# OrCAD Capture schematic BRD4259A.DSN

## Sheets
1 02: RF, Antenna & Power: size A3; title: EFR32FG14 2.4 GHz / 434 MHz 10 dBm Radio Board; rev: A01; note: BRD4259A; note: JSH; note: JNO
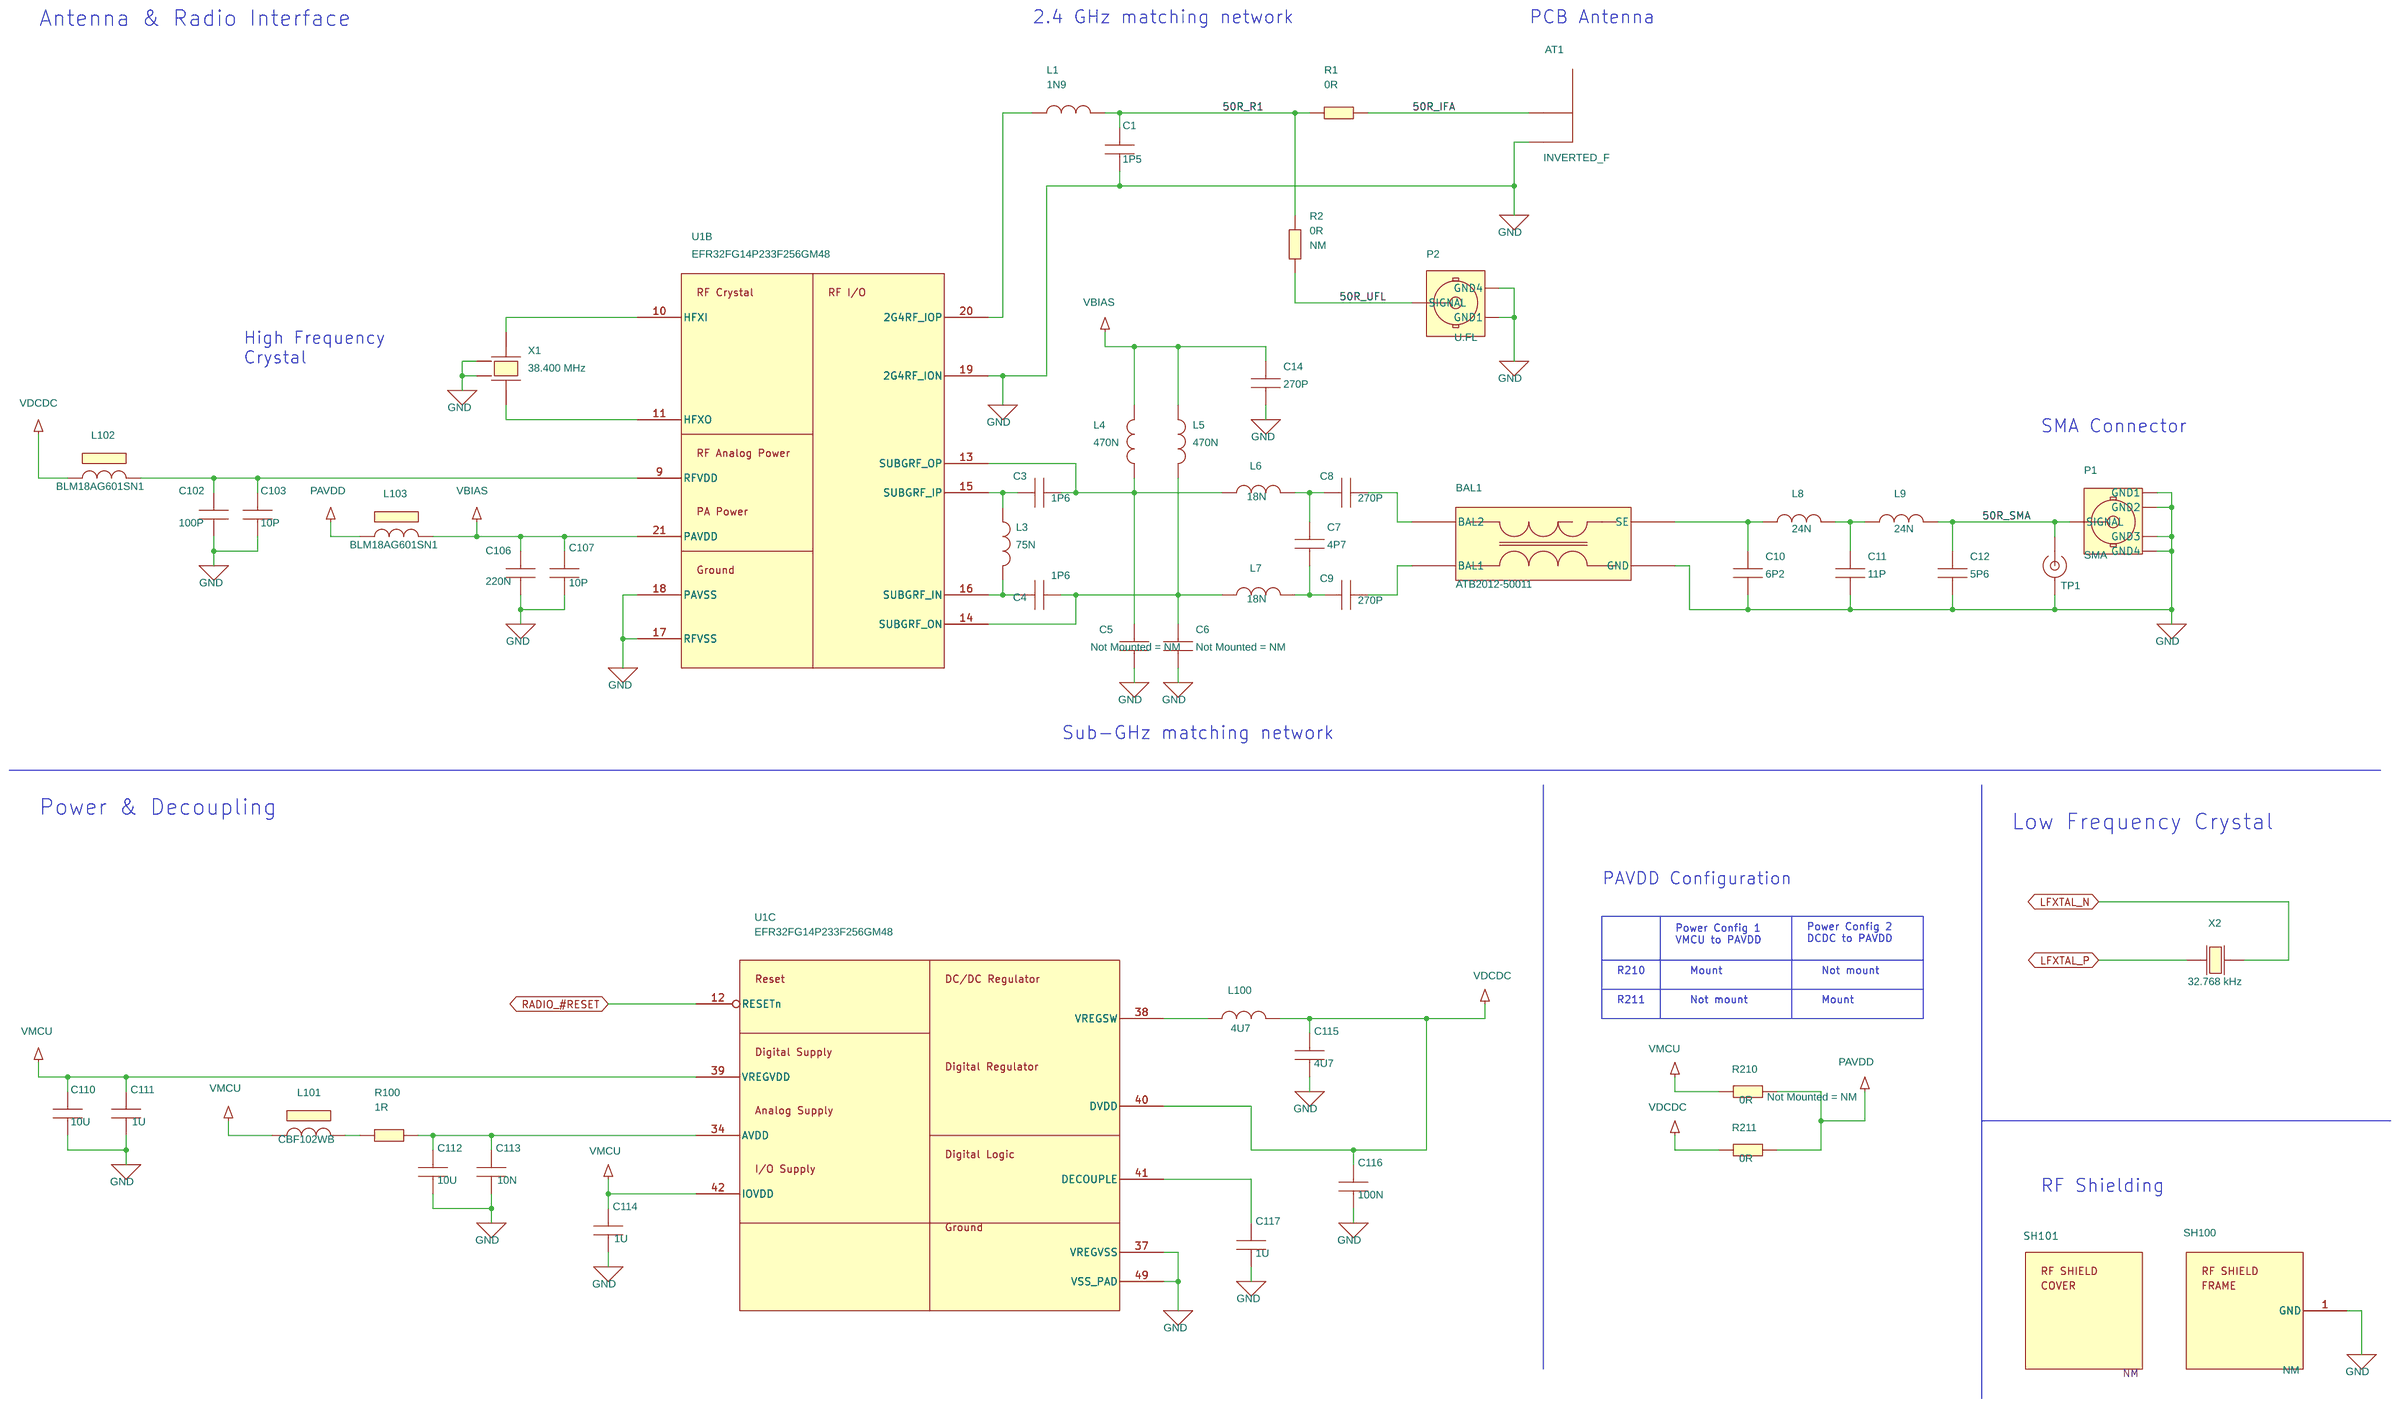
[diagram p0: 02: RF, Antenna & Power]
2 01: Title Page: company: Silicon Labs
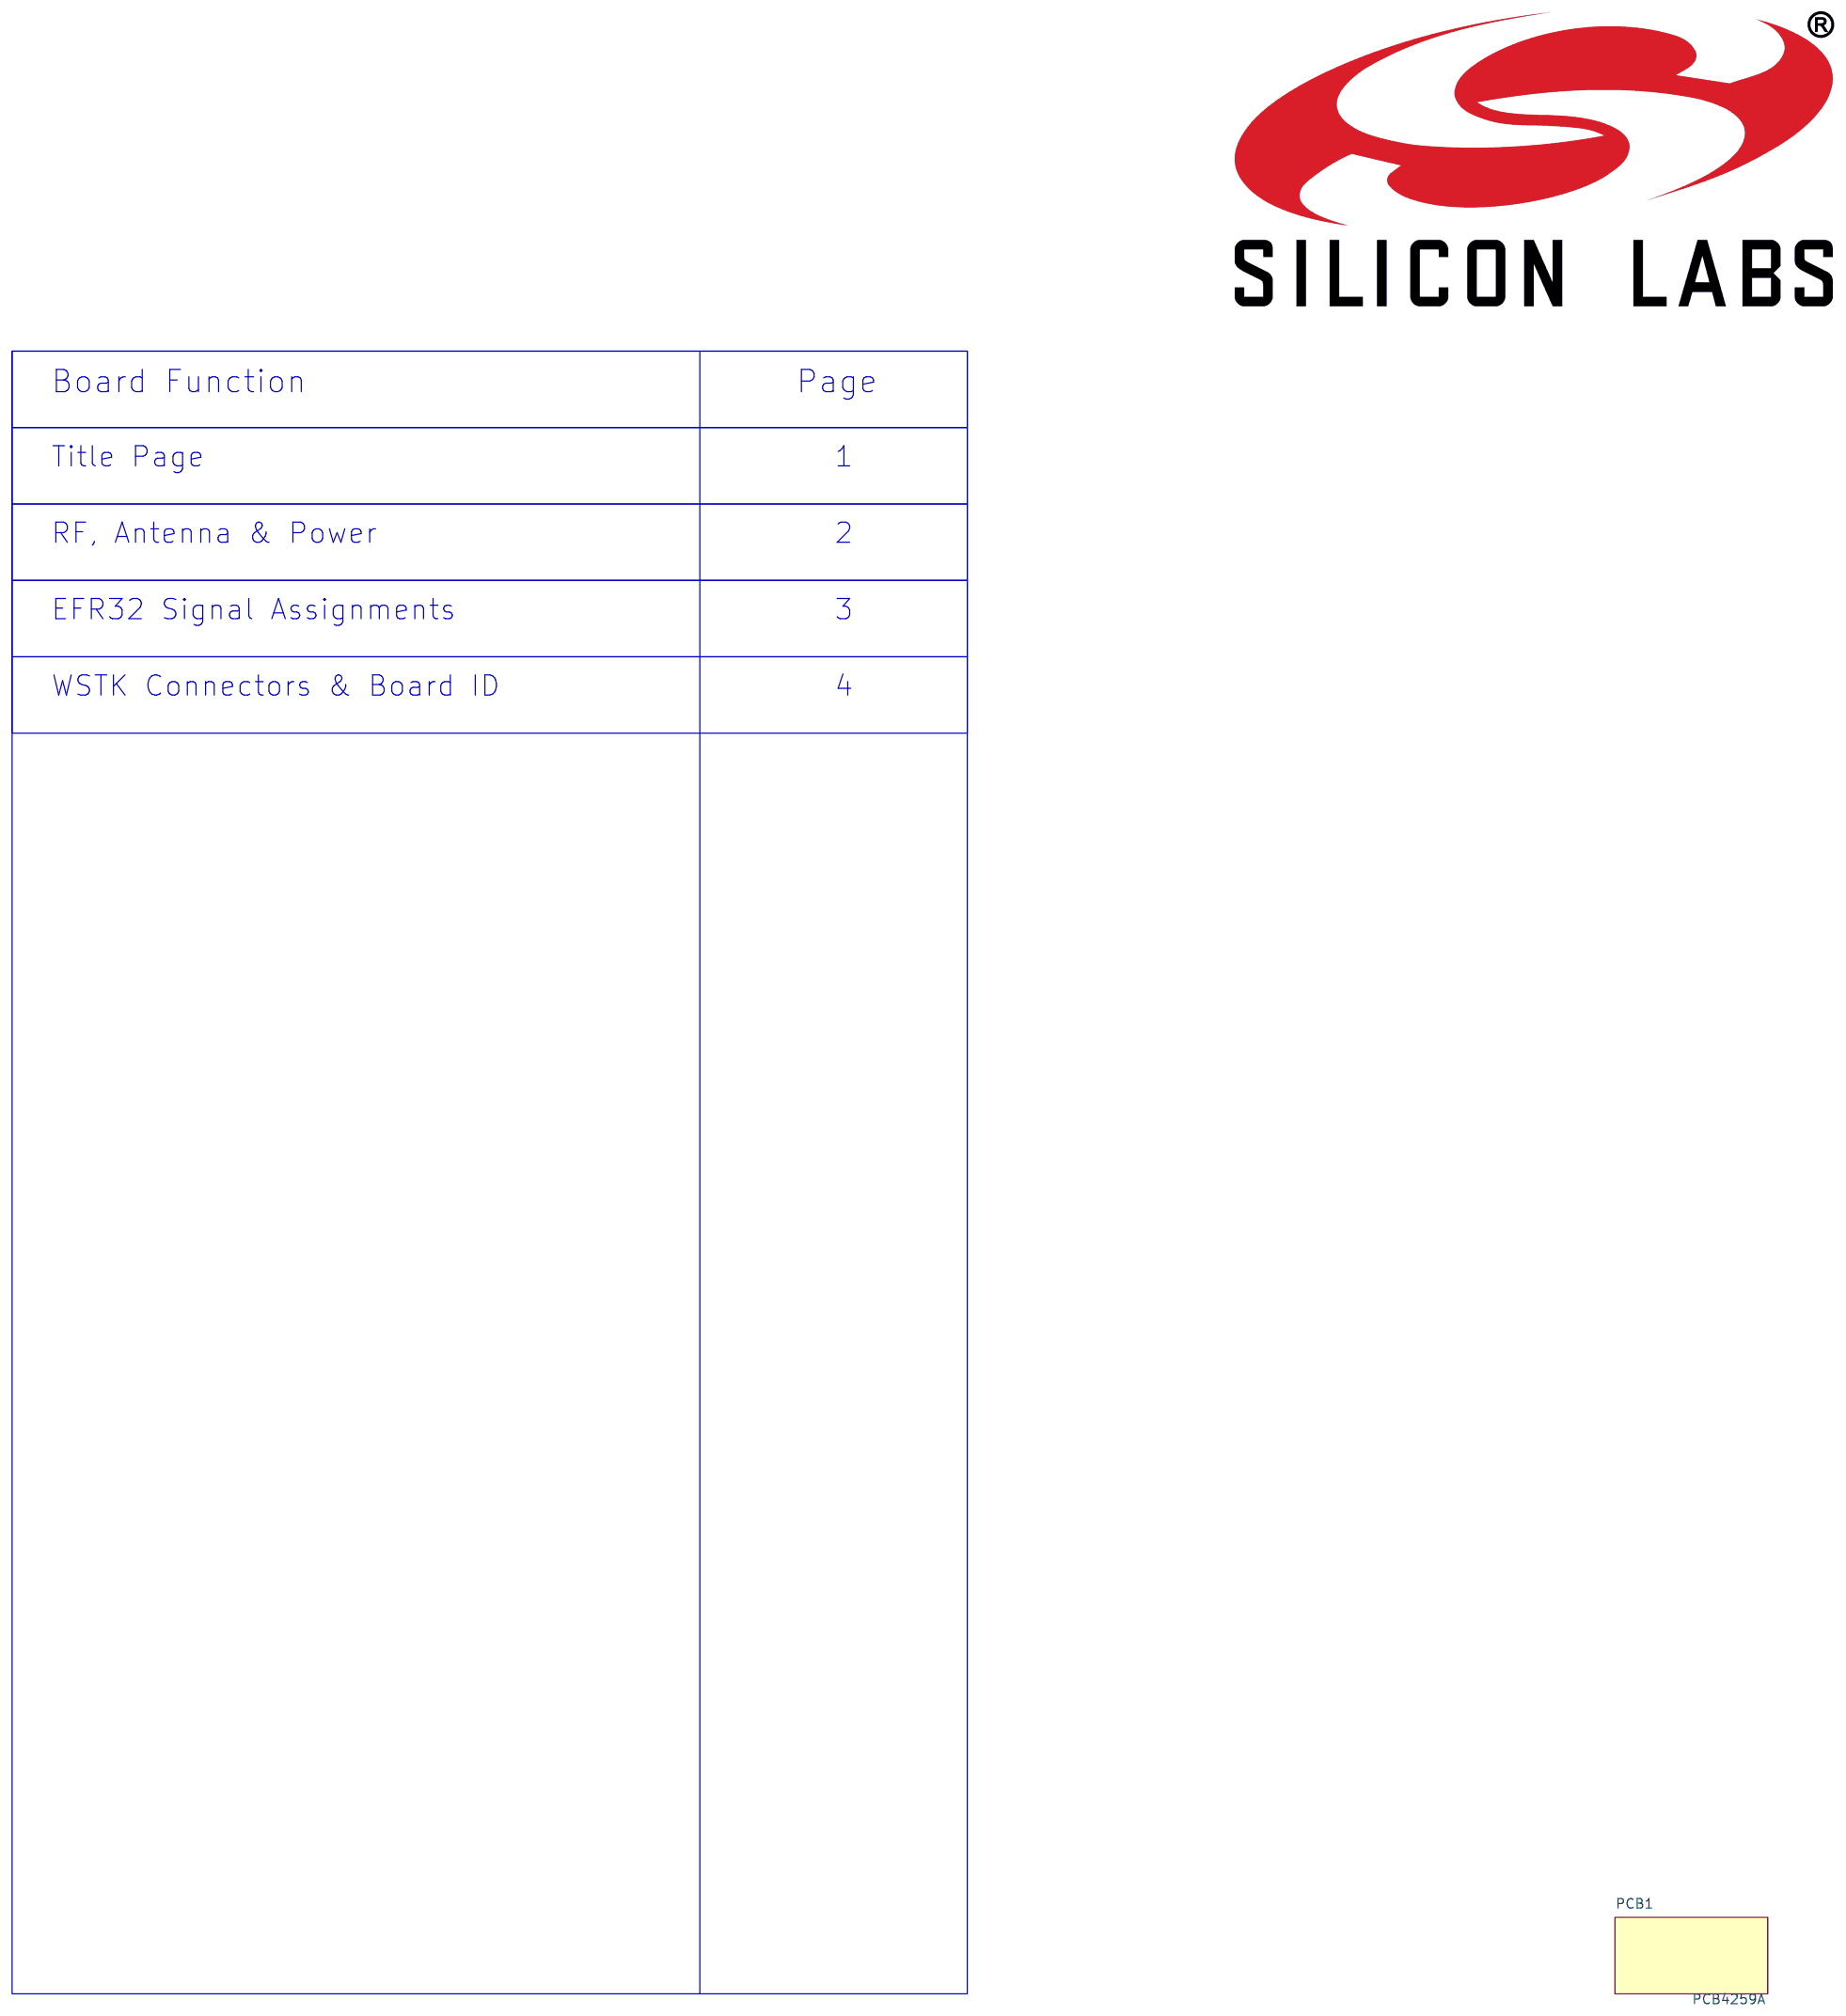
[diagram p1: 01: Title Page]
3 03: EFR32 Signal Assignments: size A3
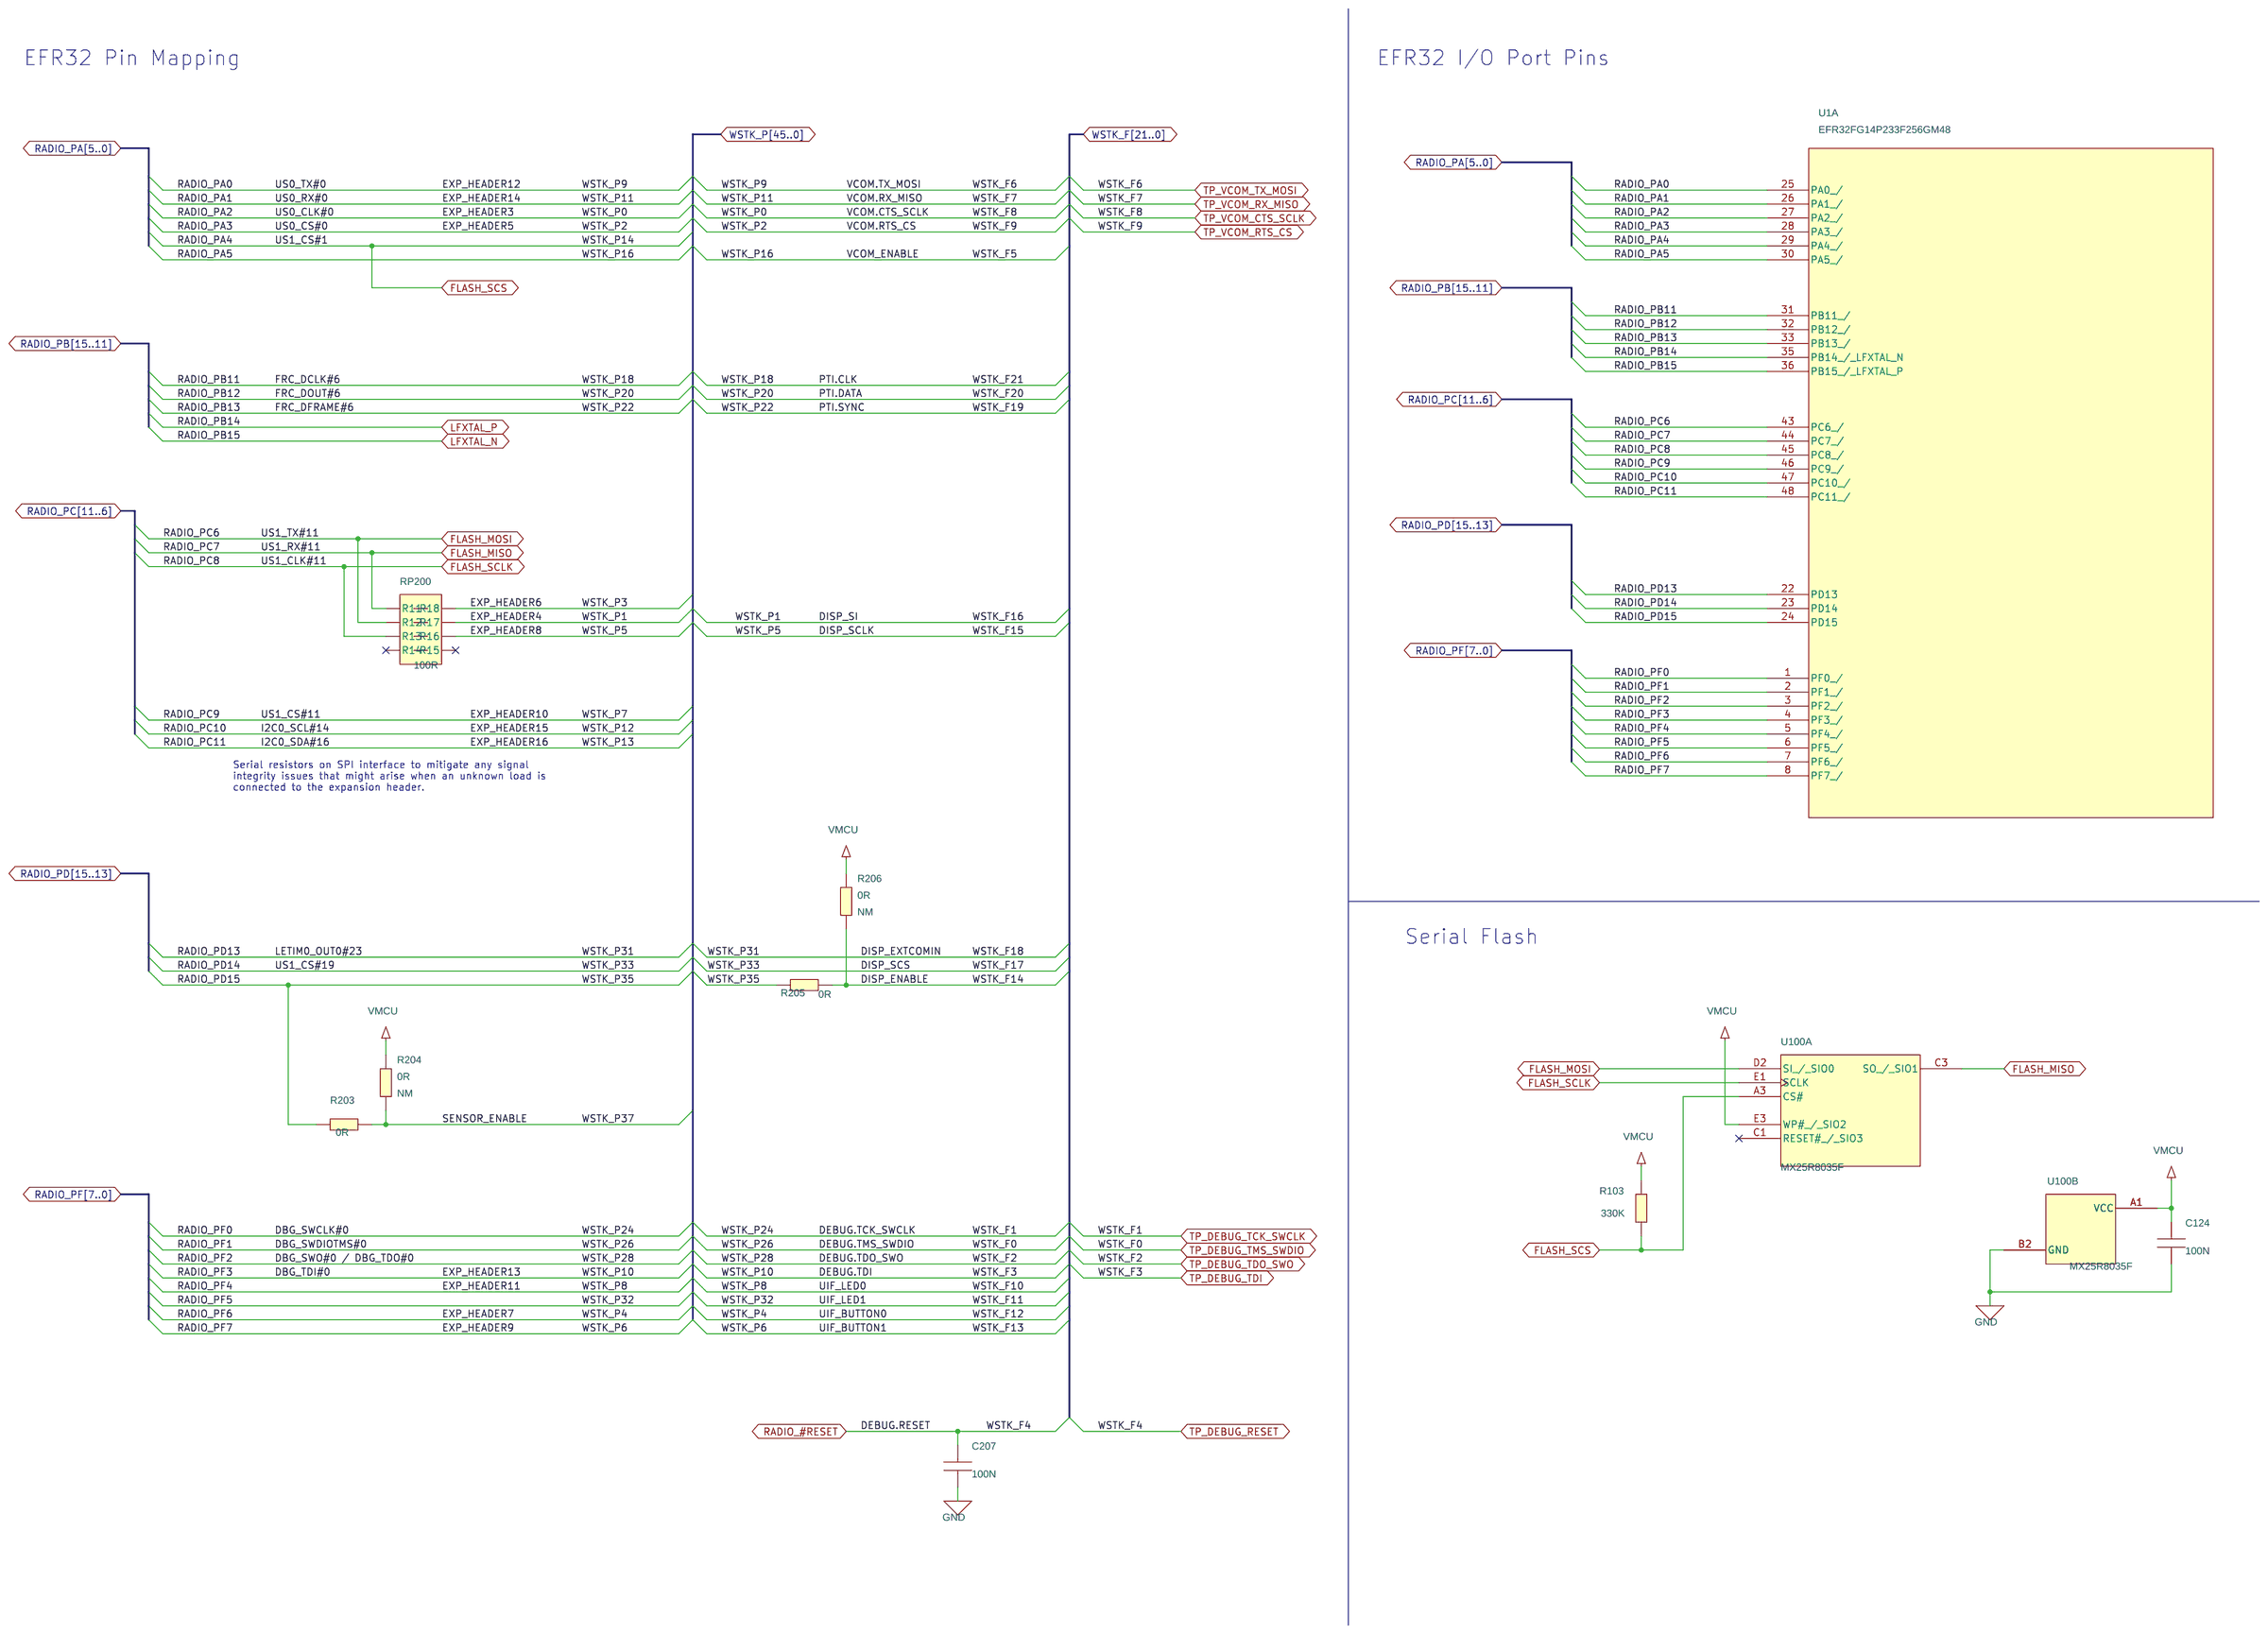
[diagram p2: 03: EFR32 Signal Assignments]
4 04: WSTK Connectors & Board ID: size A3
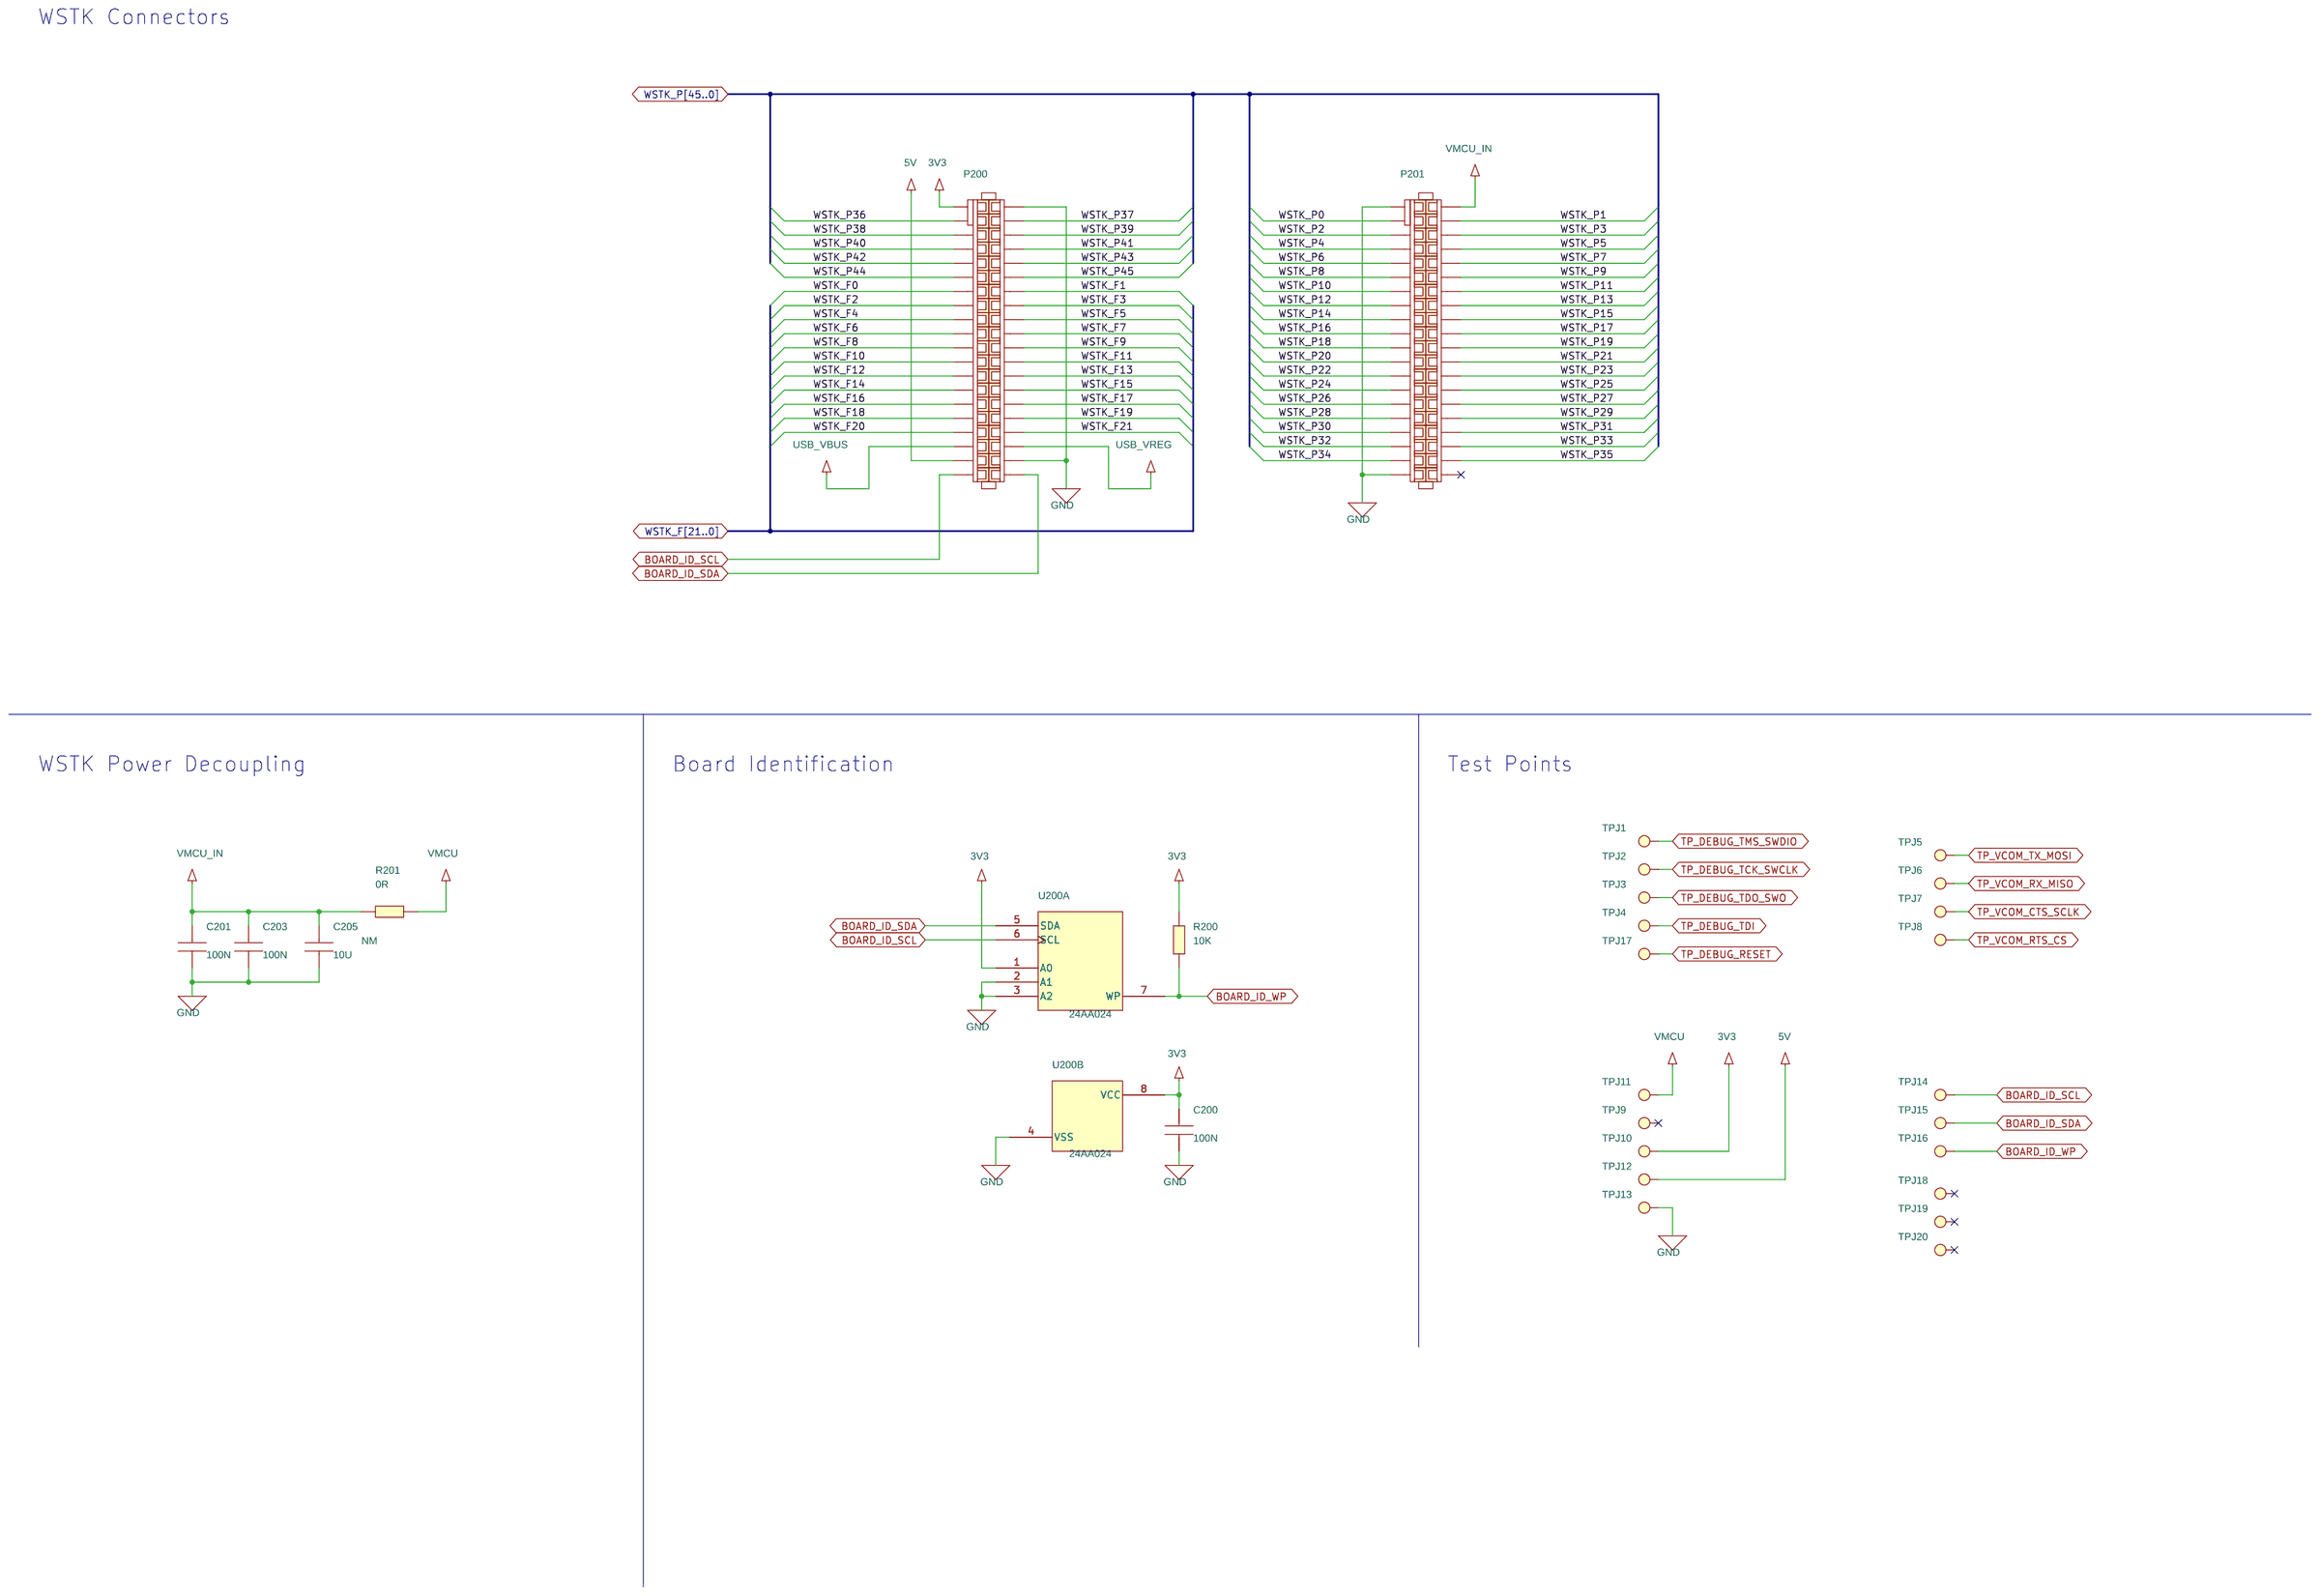
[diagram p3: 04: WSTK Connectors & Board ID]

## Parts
sheet 01: Title Page
PCB1  PCB4259A  [N/A]
sheet 02: RF, Antenna & Power
AT1  INVERTED_F  [EM358x_INVERTED_F]
BAL1  ATB2012-50011  [TDK_ATB2012]
C1  1P5  [C0402_L]
C3  1P6  [C0402_L]
C4  1P6  [C0402_L]
C5  Unused  [C0402_L]
C6  Unused  [C0402_L]
C7  4P7  [C0402_L]
C8  270P  [C0402_L]
C9  270P  [C0402_L]
C10  6P2  [C0402_L]
C11  11P  [C0402_L]
C12  5P6  [C0402_L]
C14  270P  [C0402_L]
C102  100P  [C0402_L]
C103  10P  [C0402_L]
C106  220N  [C0402_L]
C107  10P  [C0402_L]
C110  10U  [C0603_L]
C111  1U  [C0402_L]
C112  10U  [C0603_L]
C113  10N  [C0402_L]
C114  1U  [C0402_L]
C115  4U7  [C0402_L]
C116  100N  [C0402_L]
C117  1U  [C0402_L]
L1  1N9  [COIL_0402_L]
L3  75N  [COIL_0603_L]
L4  470N  [COIL_0603_L]
L5  470N  [COIL_0603_L]
L6  18N  [COIL_0402_L]
L7  18N  [COIL_0402_L]
L8  24N  [COIL_0402_L]
L9  24N  [COIL_0402_L]
L100  4U7  [COIL_MUR_LQH3NP_1212]
L101  CBF102WB  [WURTH_CBF_0603]
L102  BLM18AG601SN1  [COIL_MUR_BLM18_0603]
L103  BLM18AG601SN1  [COIL_MUR_BLM18_0603]
P1  SMA  [TE_SMA_TH_1814832]
P2  U.FL  [HIROSE_U.FL-R-SMT-1]
R1  0R  [R0402_L]
R2  0R  [R0402_L]
R100  1R  [R0402_L]
R210  0R  [R0402_L]
R211  0R  [R0402_L]
SH100  RF_SHIELD_FRAME_BMI-S-203-F  [LAIRD_BMI-S-203-F]
SH101  RF_SHIELD_COVER_BMI-S-203-C
TP1  RF_TEST_POINT  [TP_INGUN_50OHM_PARTIAL]
X1  38.400 MHz  [X_SSS_DSX211SH_2.05X1.65-4]
X2  32.768 kHz  [X_MCS_CM8V-T1A]
sheet 03: EFR32 Signal Assignments
C124  100N  [C0402_L]
C207  100N  [C0402_L]
R103  330K  [R0402_L]
R203  0R  [R0402_L]
R204  0R  [R0402_L]
R205  0R  [R0402_L]
R206  0R  [R0402_L]
RP200  100R  [RES_MNR04-8]
U1  EFR32FG14P233F256GM48  [QFN48_M050_SQ7.0_EP_SL_L]  (sections A,B,C)
U100  MX25R8035F  [BGA8_M040_1.24x1.75_WLCSP]  (sections A,B)
sheet 04: WSTK Connectors & Board ID
C200  100N  [C0402_L]
C201  100N  [C0402_L]
C203  100N  [C0402_L]
C205  10U  [C0805_L]
P200  SOCKET_2X20_1.27MM_SMD  [SAM_SFC-120-T2-D-A-2X20_SNUM]
P201  SOCKET_2X20_1.27MM_SMD  [SAM_SFC-120-T2-D-A-2X20_SNUM]
R200  10K  [T_0402]
R201  0R  [R0402_L]
TPJ1  TPJ_SMD  [TP_1.0_SMD]
TPJ2  TPJ_SMD  [TP_1.0_SMD]
TPJ3  TPJ_SMD  [TP_1.0_SMD]
TPJ4  TPJ_SMD  [TP_1.0_SMD]
TPJ5  TPJ_SMD  [TP_1.0_SMD]
TPJ6  TPJ_SMD  [TP_1.0_SMD]
TPJ7  TPJ_SMD  [TP_1.0_SMD]
TPJ8  TPJ_SMD  [TP_1.0_SMD]
TPJ9  TPJ_SMD  [TP_1.0_SMD]
TPJ10  TPJ_SMD  [TP_1.0_SMD]
TPJ11  TPJ_SMD  [TP_1.0_SMD]
TPJ12  TPJ_SMD  [TP_1.0_SMD]
TPJ13  TPJ_SMD  [TP_1.0_SMD]
TPJ14  TPJ_SMD  [TP_1.0_SMD]
TPJ15  TPJ_SMD  [TP_1.0_SMD]
TPJ16  TPJ_SMD  [TP_1.0_SMD]
TPJ17  TPJ_SMD  [TP_1.0_SMD]
TPJ18  TPJ_SMD  [TP_1.0_SMD]
TPJ19  TPJ_SMD  [TP_1.0_SMD]
TPJ20  TPJ_SMD  [TP_1.0_SMD]
U200  24AA024  [TDFN8_M050_2.0X3.0_EP]  (sections A,B)

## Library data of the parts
PCB1 = PCB: Mfg #: PCB4259A Rev. A00
AT1 = ANT_INVERTED_F
BAL1 = ATB2012-50011
C1 = C0402: Mfg: Murata; Mfg #: GRM1555C1H1R5WA01D; Technology: C0G; Tolerance: ±0.05P
C3 C4 = C0402: Mfg: Murata; Mfg #: GRM1555C1H1R6WA01D; Technology: C0G; Tolerance: ±0.05P
C5 C6 = C0402: Not Mounted: NM
C7 = C0402: Mfg: Murata; Mfg #: GRM1555C1H4R7WA01D; Technology: C0G; Tolerance: ±0.05P
C8 C9 C14 = C0402: Mfg: Murata; Mfg #: GRM1555C1H271FA01D; Technology: C0G; Tolerance: ±1%
C10 = C0402: Mfg: Murata; Mfg #: GRM1555C1H6R2BA01D; Technology: C0G; Tolerance: ±0.1P
C11 = C0402: Mfg: Murata; Mfg #: GRM1555C1H110GA01D; Technology: C0G; Tolerance: ±2%
C12 = C0402: Mfg: Murata; Mfg #: GRM1555C1H5R6WA01D; Technology: C0G; Tolerance: ±0.05pF
C102 C103 C107 = C0402: Rating: 50V; Technology: C0G; Tolerance: 5%
C106 C113 C116 C124 C200 C201 C203 C207 = C0402: Rating: 16V; Technology: X7R; Tolerance: 10%
C110 C112 = C0603: Rating: 6.3V; Technology: X5R; Tolerance: 20%
C111 C114 C117 = C0402: Rating: 25V; Technology: X5R; Tolerance: 10%
C115 = C0402: Rating: 6.3V; Technology: X5R; Tolerance: 10%
L1 = L0402: Mfg: Murata; Mfg #: LQP15MN1N9W02D; Tolerance: ±0.05N
L3 = L0603: Mfg: Murata; Mfg #: LQW18AN75NG00D; Tolerance: ±2%
L4 L5 = L0603: Mfg: Murata; Mfg #: LQW18CNR47J00D; Tolerance: ±5%
L6 L7 = L0402: Mfg: Murata; Mfg #: LQW15AN18NG00D; Tolerance: ±2%
L8 L9 = L0402: Mfg: Murata; Mfg #: LQW15AN24NG00D; Tolerance: ±2%
L100 = LQH3NP: Mfg #: LQH3NPN4R7MM0L
L101 = CBF102WB
L102 L103 = BLM18AG
P1 = SMA_TH
P2 = HIROSE_U.FL
R1 R100 R103 R200 R201 R203 R205 R211 = R0402
R2 R204 R206 R210 = R0402: Not Mounted: NM
SH100 = RF_SHIELD_FRAME_BMI-S-203-F: Not Mounted: NM
SH101 = RF_SHIELD_COVER_BMI-S-203-C: Not Mounted: NM
TP1 = TP_RF
X1 = DSX211SH: Mfg: KDS; Mfg #: DSX211SH 1ZZNAE38400AB0A
X2 = CM8V-T1A: Mfg: KDS; Mfg #: DST210 1TJG125DP1A0012
RP200 = MNR04M0APJ101
U1 = EFR32-DUALBAND-QFN48: Mfg #: EFR32FG14P233F256GM48-BR
U100 = MX25R8035
C205 = C0805: Not Mounted: NM; Rating: 10V; Technology: X5R; Tolerance: 10%
P200 P201 = SOCKET_2X20_1.27MM_SMD
TPJ1-TPJ20 = TPJ_SMD
U200 = 24AA024

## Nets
3V3: C200.1 P200.1 R200.2 TPJ10.1(TP) U200.1(A0) U200.8(VCC)
5V: P200.37 TPJ12.1(TP)
GND: AT1.2(GND) BAL1.2(GND) C1.1 C5.2 C6.2 C10.2 C11.2 C12.2 C14.2 C102.2 C103.2 C106.2 C107.2 C110.2 C111.2 C112.2 C113.2 C114.2 C115.2 C116.2 C117.2 C124.2 C200.2 C201.2 C203.2 C205.2 C207.2 P1.2(GND1) P1.3(GND2) P1.4(GND3) P1.5(GND4) P2.2(GND1) P2.3(GND4) P200.2 P200.38 P201.1 P201.39 SH100.1(GND) TP1.2(GND) TPJ13.1(TP) U1.17(RFVSS) U1.18(PAVSS) U1.19(2G4RF_ION) U1.37(VREGVSS) U1.49(VSS_PAD) U100.B2(GND) U200.2(A1) U200.3(A2) U200.4(VSS) X1.2 X1.4
50R_IFA: AT1.1(ANT) R1.2
50R_R1: C1.2 L1.2 R1.1 R2.1
50R_SMA: C12.1 L9.1 P1.1(SIGNAL) TP1.1(RF)
50R_UFL: P2.1(SIGNAL) R2.2
BOARD_ID_SCL: P200.39 TPJ14.1(TP) U200.6(SCL)
BOARD_ID_SDA: P200.40 TPJ15.1(TP) U200.5(SDA)
BOARD_ID_WP: R200.1 TPJ16.1(TP) U200.7(WP)
FLASH_MISO: RP200.1(R11) U1.44(PC7_/) U100.C3(SO_/_SIO1)
FLASH_MOSI: RP200.2(R12) U1.43(PC6_/) U100.D2(SI_/_SIO0)
FLASH_SCLK: RP200.3(R13) U1.45(PC8_/) U100.E1(SCLK)
FLASH_SCS: P201.17 R103.2 U1.29(PA4_/) U100.A3(CS#)
LFXTAL_N: U1.36(PB15_/_LFXTAL_P) X2.1
LFXTAL_P: U1.35(PB14_/_LFXTAL_N) X2.2
PAVDD: L103.1 R210.1 R211.1
RADIO_#RESET: C207.1 P200.17 TPJ17.1(TP) U1.12(RESETn)
RADIO_PA0: P200.19 P201.12 TPJ5.1(TP) U1.25(PA0_/)
RADIO_PA1: P200.20 P201.14 TPJ6.1(TP) U1.26(PA1_/)
RADIO_PA2: P200.21 P201.3 TPJ7.1(TP) U1.27(PA2_/)
RADIO_PA3: P200.22 P201.5 TPJ8.1(TP) U1.28(PA3_/)
RADIO_PA5: P200.18 P201.19 U1.30(PA5_/)
RADIO_PB11: P200.34 P201.21 U1.31(PB11_/)
RADIO_PB12: P200.33 P201.23 U1.32(PB12_/)
RADIO_PB13: P200.32 P201.25 U1.33(PB13_/)
RADIO_PC9: P201.10 U1.46(PC9_/)
RADIO_PC10: P201.15 U1.47(PC10_/)
RADIO_PC11: P201.16 U1.48(PC11_/)
RADIO_PD13: P200.31 P201.34 U1.22(PD13)
RADIO_PD14: P200.30 P201.36 U1.23(PD14)
RADIO_PD15: P201.38 R203.1 R205.1 U1.24(PD15)
RADIO_PF0: P200.14 P201.27 TPJ2.1(TP) U1.1(PF0_/)
RADIO_PF1: P200.13 P201.29 TPJ1.1(TP) U1.2(PF1_/)
RADIO_PF2: P200.15 P201.31 TPJ3.1(TP) U1.3(PF2_/)
RADIO_PF3: P200.16 P201.13 TPJ4.1(TP) U1.4(PF3_/)
RADIO_PF4: P200.23 P201.11 U1.5(PF4_/)
RADIO_PF5: P200.24 P201.35 U1.6(PF5_/)
RADIO_PF6: P200.25 P201.7 U1.7(PF6_/)
RADIO_PF7: P200.26 P201.9 U1.8(PF7_/)
USB_VBUS: P200.35
USB_VREG: P200.36
VBIAS: C14.1 C106.1 C107.1 L4.1 L5.1 L103.2 U1.21(PAVDD)
VDCDC: C115.1 C116.1 L100.2 L102.1 R211.2 U1.40(DVDD)
VMCU: C110.1 C111.1 C114.1 C124.1 L101.1 R103.1 R201.2 R204.1 R206.1 R210.2 TPJ11.1(TP) U1.39(VREGVDD) U1.42(IOVDD) U100.A1(VCC) U100.E3(WP#_/_SIO2)
VMCU_IN: C201.1 C203.1 C205.1 P201.2 R201.1
WSTK_F14: P200.27 R205.2 R206.2
WSTK_F15: P200.28 P201.8 RP200.6(R16)
WSTK_F16: P200.29 P201.4 RP200.7(R17)
WSTK_P3: P201.6 RP200.8(R18)
WSTK_P15: P201.18
WSTK_P17: P201.20
WSTK_P19: P201.22
WSTK_P21: P201.24
WSTK_P23: P201.26
WSTK_P25: P201.28
WSTK_P27: P201.30
WSTK_P29: P201.32
WSTK_P30: P201.33
WSTK_P34: P201.37
WSTK_P36: P200.3
WSTK_P37: P200.4 R203.2 R204.2
WSTK_P38: P200.5
WSTK_P39: P200.6
WSTK_P40: P200.7
WSTK_P41: P200.8
WSTK_P42: P200.9
WSTK_P43: P200.10
WSTK_P44: P200.11
WSTK_P45: P200.12
N17603239: L1.1 U1.20(2G4RF_IOP)
N17603622: U1.11(HFXO) X1.1
N17603629: U1.10(HFXI) X1.3
N17769146: C117.1 U1.41(DECOUPLE)
N17769405: L100.1 U1.38(VREGSW)
N17853356: C102.1 C103.1 L102.2 U1.9(RFVDD)
N17857389: L101.2 R100.1
N17857391: C112.1 C113.1 R100.2 U1.34(AVDD)
N18038575: C3.2 L3.1 U1.15(SUBGRF_IP)
N18038577: C4.2 L3.2 U1.16(SUBGRF_IN)
N18038619: C3.1 C5.1 L4.2 L6.2 U1.13(SUBGRF_OP)
N18038621: C4.1 C6.1 L5.2 L7.2 U1.14(SUBGRF_ON)
N18038649: C7.1 C8.2 L6.1
N18038653: C7.2 C9.2 L7.1
N18038740: C11.1 L8.1 L9.2
N18038746: BAL1.1(SE) C10.1 L8.2
N18038850: BAL1.4(BAL2) C8.1
N18038856: BAL1.3(BAL1) C9.1

Not connected (* = marked no-connect by the designer): P201 40*; RP200 4(R14)* 5(R15)*; TPJ9 1(TP)*; TPJ18 1(TP)*; TPJ19 1(TP)*; TPJ20 1(TP)*; U100 C1(RESET#_/_SIO3)*

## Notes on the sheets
sheet 1
- Antenna & Radio Interface
- 2.4 GHz matching network
- PCB Antenna
- High Frequency
  Crystal
- SMA Connector
- Sub-GHz matching network
- Power & Decoupling
- Low Frequency Crystal
- PAVDD Configuration
- Power Config 1
  VMCU to PAVDD
- Power Config 2
  DCDC to PAVDD
- R210
- Mount
- Not mount
- R211
- Not mount
- Mount
- RF Shielding
sheet 2
- Board Function
- Page
- Title Page
- 1
- RF, Antenna & Power
- 2
- EFR32 Signal Assignments
- 3
- WSTK Connectors & Board ID
- 4
sheet 3
- EFR32 Pin Mapping
- EFR32 I/O Port Pins
- Serial resistors on SPI interface to mitigate any signal
  integrity issues that might arise when an unknown load is
  connected to the expansion header.
- Serial Flash
sheet 4
- WSTK Connectors
- WSTK Power Decoupling
- Board Identification
- Test Points
